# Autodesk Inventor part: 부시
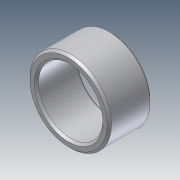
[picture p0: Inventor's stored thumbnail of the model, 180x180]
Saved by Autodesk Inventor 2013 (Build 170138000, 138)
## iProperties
Company: 한국ATC센터
Created: 2013-01
Part Number: 부시
Document SubType Name: Modeling
Designer: KYOUNG IL JANG
Density: 1 g/cm^3
Material: 일반
Author: KYOUNG IL JANG
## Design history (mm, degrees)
sketch "스케치1"
  geometry: L1 (15, 20)-(15, -46) reference; L2 (-20, 19)-(20, 19); L3 (30.7, -1)-(-30.7, -1) reference; L4 (19, 19)-(19, -1); L5 (15, -1)-(19, -1); L6 (0, 0)-(0, 19); L7 (19, 19)-(15, 19)
  constraints: 12 end point, 6 point on line, 1 collinear, 1 midpoint, 1 perpendicular, 1 vertical, 2 other
  dimensions: "d0" = 38 diameter of L4 L6; "d5" = 20 distance between parallel lines of L2 L3
revolve "회전1" sketch "스케치1" stored, may be unused: angle "d1" = 90 deg
chamfer "모따기1" distance "d2" = 1; stored, may be unused: second distance "d3" = 2, angle "d4" = 45 deg
node "솔리드1"
node "참조2"
